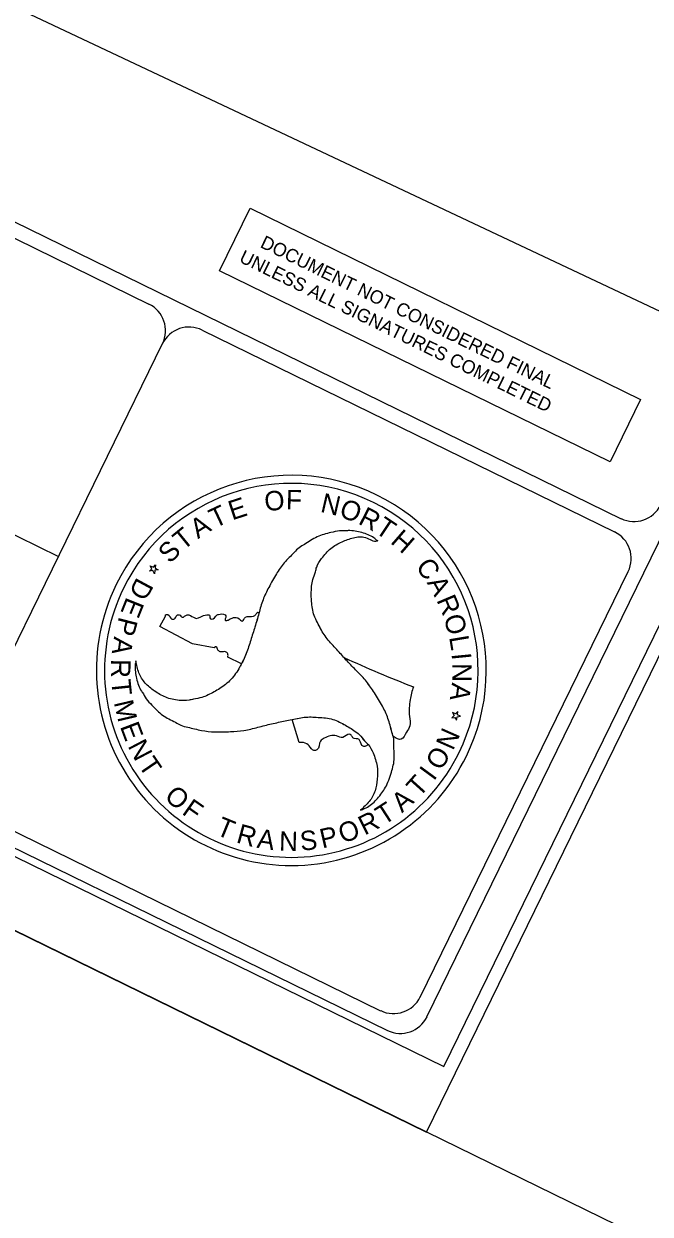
# Model space of a CAD drawing. Extents: x 1517888 to 1526099, y 633375 to 640181.
# Drawn here: x 1520641 to 1521065, y 636669 to 637474 of the extents above; entities that cross this region are included whole.
import ezdxf

# ---------------------------------------------------------------- set-up
doc = ezdxf.new("R2010")
doc.units = 0
for name, color, linetype in [('Sheet Clip Boundary CELL', 7, 'Continuous'), ('Sheet Cutting Line CELL', 7, 'Continuous'), ('Sheet Plot Border Inside CELL', 7, 'Continuous'), ('Sheet Plot Border Outside CELL', 7, 'Continuous'), ('Sheet Sticker Exception Certification CELL', 7, 'Continuous'), ('Sheet Title CELL', 7, 'Continuous')]:
    doc.layers.add(name, color=color, linetype=linetype)

msp = doc.modelspace()

# ---------------------------------------------------------------- linework, layer by layer
at = {"layer": 'Sheet Clip Boundary CELL'}
msp.add_lwpolyline([(1519997.22, 638878.25), (1520677.94, 638519.75), (1521000.39, 638385.3), (1521102.69, 638308.65), (1521171.04, 638278.93), (1521395.99, 638165.98), (1521492.2, 638121.51), (1521760.41, 637993.13), (1521455.66, 637316.28), (1521359.72, 637143.34), (1520289.98, 637647.3), (1519534.36, 638030.12)], close=True, dxfattribs=at)
at = {"layer": 'Sheet Cutting Line CELL'}
msp.add_line((1518399.92, 637954.19), (1521425.45, 636474.47), dxfattribs=at)
at = {"layer": 'Sheet Plot Border Inside CELL'}
msp.add_lwpolyline([(1517931.1, 638233.43), (1520925.19, 636769.09), (1521852.3, 638664.72), (1518858.21, 640129.06)], close=True, dxfattribs=at)
at = {"layer": 'Sheet Plot Border Outside CELL'}
msp.add_lwpolyline([(1521880.11, 638701.1), (1518854.58, 640180.82), (1517888.03, 638204.54), (1520913.56, 636724.82)], close=True, dxfattribs=at)
at = {"layer": 'Sheet Sticker Exception Certification CELL'}
for p, q in [((1520773.47, 637306.71), (1520794.12, 637348.93)), ((1520794.12, 637348.93), (1521058.22, 637219.77)), ((1521037.57, 637177.55), (1520773.47, 637306.71)), ((1521058.21, 637219.74), (1521037.56, 637177.52))]:
    msp.add_line(p, q, dxfattribs=at)
at = {"layer": 'Sheet Title CELL'}
for p, q in [((1518493.77, 638386.96), (1521044.99, 637139.22)), ((1520366.85, 637459.74), (1520725.77, 637284.21)), ((1520268.21, 637307.67), (1520664.67, 637113.77)), ((1520761.7, 637266.63), (1521040.59, 637130.23)), ((1520594.36, 636969.99), (1520734.95, 637257.45)), ((1520880.48, 637124.39), (1520880.15, 637124.24)), ((1520880.48, 637124.39), (1520880.15, 637124.24)), ((1520726.19, 637103.66), (1520727.75, 637105.33)), ((1520727.75, 637105.33), (1520726.7, 637107.37)), ((1520726.7, 637107.37), (1520728.77, 637106.35)), ((1520728.77, 637106.35), (1520730.26, 637107.97)), ((1520730.26, 637107.97), (1520730.03, 637105.74)), ((1520730.03, 637105.74), (1520732.07, 637104.74)), ((1520728.37, 637104.11), (1520726.19, 637103.66)), ((1520729.46, 637102.06), (1520728.37, 637104.11)), ((1520729.78, 637104.34), (1520729.46, 637102.06)), ((1520732.07, 637104.74), (1520729.78, 637104.34)), ((1520733.19, 637066.4), (1520736.92, 637073.41)), ((1520755.24, 637054.58), (1520733.19, 637066.4)), ((1520769.97, 637052.07), (1520755.24, 637054.58)), ((1520788.46, 637041.07), (1520779.14, 637045.76)), ((1520857.59, 637045.48), (1520857.59, 637045.48)), ((1520934.6, 637008.86), (1520933.04, 637007.28)), ((1520934.38, 637006.62), (1520934.6, 637008.86)), ((1520827.38, 636987.99), (1520822.72, 637003.62)), ((1520822.72, 637003.62), (1520822.72, 637003.62)), ((1520932.11, 637006.25), (1520930.55, 637004.58)), ((1520930.55, 637004.58), (1520932.71, 637005)), ((1520933.04, 637007.28), (1520931.01, 637008.27)), ((1520931.01, 637008.27), (1520932.11, 637006.25)), ((1520932.71, 637005), (1520933.78, 637003)), ((1520933.78, 637003), (1520934.14, 637005.26)), ((1520934.14, 637005.26), (1520936.41, 637005.72)), ((1520936.41, 637005.72), (1520934.38, 637006.62)), ((1520940.46, 636978.86), (1520940.46, 636978.86))]:
    msp.add_line(p, q, dxfattribs=at)
for points in [[(1520913.77, 636802.64), (1521818.82, 638653.15)], [(1518227.99, 638093.91), (1520887.01, 636793.44)], [(1520909.18, 636816.02), (1521049.77, 637103.48)], [(1520603.54, 636943.23), (1520882.43, 636806.84)]]:
    msp.add_lwpolyline(points, dxfattribs=at)
for centre, radius, start, end in [((1520716.98, 637266.24), 20, 333.93772, 63.93772), ((1520752.92, 637248.67), 20, 63.93772, 153.93772), ((1520822.06, 637036.74), 131.79, 333.93772, 153.93772), ((1520822.06, 637036.74), 126.3, 333.93772, 153.93772), ((1521053.82, 637157.26), 20, 243.93772, 333.93772), ((1521031.85, 637112.34), 20, 333.93772, 63.93772), ((1520822.06, 637036.74), 131.79, 153.93772, 333.93772), ((1520822.06, 637036.74), 126.3, 153.93772, 333.93772), ((1521150.64, 637675.53), 694.86, 239.61622, 239.71581), ((1521150.64, 637675.53), 694.86, 245.05527, 249.26128), ((1520891.26, 636824.88), 20, 243.93772, 333.93772), ((1520895.85, 636811.51), 20, 243.93772, 333.93772)]:
    msp.add_arc(centre, radius, start, end, dxfattribs=at)
for points in [[(1520880.15, 637124.24), (1520877.83, 637126.25), (1520869.81, 637129.78), (1520860.56, 637131.13), (1520859.67, 637131.09), (1520854.64, 637130.94), (1520848.85, 637129.86), (1520839.46, 637126.93), (1520830.89, 637121.86), (1520827.36, 637119.62), (1520824, 637116.4), (1520817.28, 637109.33), (1520811.97, 637101.93), (1520806.82, 637092.75), (1520802.91, 637084.4), (1520800.15, 637075.27), (1520797.45, 637066.03), (1520794.63, 637057.14), (1520791.62, 637048.05), (1520787.51, 637039.58), (1520787.12, 637038.86), (1520781.2, 637030.58), (1520773.69, 637024.47), (1520765.74, 637020.13), (1520761.48, 637018.44), (1520756, 637017.29), (1520752.88, 637016.6), (1520746.17, 637016.48), (1520737.14, 637018.55), (1520729.43, 637022.89), (1520723.29, 637028.11), (1520719.05, 637035.1), (1520716.96, 637043.17)], [(1520868.87, 636942.39), (1520871.62, 636943.39), (1520878.76, 636948.55), (1520884.56, 636955.89), (1520885.06, 636956.65), (1520887.35, 636961.14), (1520889.34, 636966.73), (1520891.58, 636976.29), (1520891.35, 636986.23), (1520891.26, 636990.4), (1520890.12, 636995), (1520887.37, 637004.31), (1520883.64, 637012.61), (1520878.22, 637021.61), (1520872.89, 637029.13), (1520866.4, 637036.22), (1520859.77, 637043.11), (1520853.55, 637049.94), (1520847.05, 637057.2), (1520841.83, 637064.93), (1520841.46, 637065.68), (1520837.15, 637075), (1520835.65, 637084.56), (1520835.8, 637093.58), (1520836.58, 637098.02), (1520838.33, 637103.39), (1520839.21, 637106.52), (1520842.55, 637112.28), (1520848.87, 637119.15), (1520856.4, 637123.6), (1520864.01, 637126.27), (1520872.22, 637126.43), (1520880.15, 637124.24), (1520880.48, 637124.39)], [(1520736.92, 637073.41), (1520737, 637074.19), (1520738.57, 637074.38), (1520741.24, 637071.38), (1520743.63, 637072), (1520744.26, 637073.47), (1520746.3, 637074.26), (1520748.35, 637072.69), (1520751.71, 637074.31), (1520753.83, 637073.84), (1520757.83, 637071.88), (1520764.9, 637074.33), (1520767.04, 637073.64), (1520766.91, 637072.13), (1520768.02, 637071.29), (1520771.98, 637074.22), (1520772.78, 637074.53), (1520777.22, 637074.18), (1520777.86, 637073), (1520777.28, 637071.11), (1520777.63, 637070.5), (1520779.29, 637070.77), (1520781.97, 637072.07), (1520785.8, 637072.16), (1520789.06, 637070.04), (1520791.05, 637072.59), (1520796.46, 637073.34), (1520798.11, 637074.57), (1520799.14, 637076.16)], [(1520800.21, 637075.5), (1520800.15, 637075.27), (1520797.45, 637066.03), (1520794.63, 637057.14), (1520791.62, 637048.05), (1520788.43, 637041.09)], [(1520779.14, 637045.76), (1520779.07, 637047.92), (1520777.51, 637049.34), (1520774.41, 637049.24), (1520772.61, 637050.26), (1520771.29, 637052.73), (1520769.97, 637052.07)], [(1520716.96, 637043.17), (1520716.49, 637040.09), (1520717.41, 637031.38), (1520720.81, 637022.67), (1520721.3, 637022), (1520723.98, 637017.6), (1520727.82, 637013.2), (1520735.05, 637006.45), (1520743.68, 637001.7), (1520747.35, 636999.69), (1520752.05, 636998.35), (1520761.32, 636996.16), (1520770.33, 636995.19), (1520780.93, 636995.35), (1520790.03, 636996.17), (1520799.42, 636998.31), (1520808.75, 637000.66), (1520817.87, 637002.6), (1520827.27, 637004.48), (1520836.64, 637005.24), (1520837.61, 637005.16), (1520847.75, 637004.2), (1520856.69, 637000.79), (1520864.34, 636996.17), (1520868.09, 636993.25), (1520871.64, 636989.04), (1520874.02, 636986.7), (1520877.34, 636980.95), (1520880.02, 636972.11), (1520880.16, 636963.35), (1520878.68, 636955.33), (1520874.74, 636948.17), (1520868.87, 636942.39)], [(1520891, 636992.09), (1520890.12, 636995), (1520887.37, 637004.31), (1520883.64, 637012.61), (1520878.22, 637021.61), (1520872.89, 637029.13), (1520866.4, 637036.22), (1520859.77, 637043.11), (1520857.59, 637045.48)], [(1520904.56, 637025.68), (1520902.39, 637016.96), (1520901.98, 637005.64), (1520902.16, 636999.25), (1520899.94, 636994.9), (1520896.37, 636990.17), (1520891.06, 636992.11)], [(1520822.72, 637003.62), (1520827.27, 637004.48), (1520836.64, 637005.24), (1520837.61, 637005.16), (1520847.75, 637004.2), (1520856.69, 637000.79), (1520864.34, 636996.17), (1520868.09, 636993.25), (1520871.64, 636989.04), (1520873.82, 636986.84)], [(1520873.77, 636986.82), (1520871.67, 636985.28), (1520869.81, 636986.02), (1520867.91, 636990.04), (1520863.71, 636991.14), (1520862.45, 636993.01), (1520861.31, 636993.61), (1520856.84, 636991.5), (1520852.64, 636992.51), (1520844.28, 636990.98), (1520841.73, 636988.97), (1520839.41, 636983.06), (1520837.35, 636982.68), (1520835.66, 636983.85), (1520832.59, 636987.18), (1520827.38, 636987.99)]]:
    msp.add_spline(points, degree=3, dxfattribs=at)

# ---------------------------------------------------------------- texts
at = {"layer": 'Sheet Sticker Exception Certification CELL'}
for s, p in [('DOCUMENT NOT CONSIDERED FINAL', (1520800.37, 637322.84)), ('UNLESS ALL SIGNATURES COMPLETED', (1520786.18, 637312.99))]:
    msp.add_text(s, height=9, rotation=333.93772, dxfattribs=at).set_placement(p)
at = {"layer": 'Sheet Title CELL'}
for s, height, rotation, p in [('E', 13.1, 18.09466, (1520782.04, 637138.01)), ('O', 13.16, 6.15528, (1520804.52, 637144.14)), ('F', 13.17, 359.00844, (1520818.35, 637145.56)), ('N', 13.14, 346.9215, (1520841.16, 637143.92)), ('T', 13.11, 25.21029, (1520770.38, 637132.58)), ('O', 13.17, 339.42339, (1520853.66, 637140.94)), ('R', 13.14, 332.81346, (1520866.66, 637136.06)), ('A', 13.18, 32.26551, (1520758.88, 637125.33)), ('T', 13.17, 326.16383, (1520877.86, 637130.32)), ('T', 13.17, 39.31782, (1520748.84, 637117.33)), ('H', 13.12, 319.07911, (1520888.49, 637123.08)), ('S', 13.13, 45.69397, (1520740.07, 637108.39)), ('C', 13.1, 306.73676, (1520905.65, 637106.6)), ('D', 13.14, 241.79072, (1520717.78, 637100.16)), ('A', 13.13, 299.23973, (1520913.45, 637096.04)), ('E', 13.08, 248.07861, (1520710.77, 637086.81)), ('R', 13.13, 292.87579, (1520920.05, 637084.29)), ('O', 13.16, 285.75618, (1520924.9, 637072.7)), ('P', 13.14, 255.61101, (1520705.69, 637073.47)), ('A', 13.12, 262.20358, (1520702.21, 637059.86)), ('L', 13.11, 279.52251, (1520928.71, 637059.23)), ('R', 13.14, 269.27222, (1520700.26, 637044.42)), ('I', 13.16, 275.53316, (1520930.35, 637047.99)), ('N', 13.14, 269.83306, (1520930.87, 637041.6)), ('T', 13.13, 275.92275, (1520700.21, 637029.92)), ('A', 13.14, 262.40108, (1520930.74, 637028.71)), ('M', 13.1, 283.15779, (1520701.97, 637015.1)), ('E', 13.11, 290.62456, (1520706.04, 636998.89)), ('N', 13.14, 66.14586, (1520931.38, 636982.09)), ('N', 13.17, 297.59611, (1520711.19, 636985.68)), ('T', 13.12, 304.43811, (1520718.19, 636972.6)), ('O', 13.09, 58.89784, (1520923.3, 636968.42)), ('I', 13.17, 53.76221, (1520918.39, 636961.57)), ('T', 13.12, 48.11231, (1520908.52, 636950.48)), ('O', 13.13, 317.74179, (1520735.55, 636950.58)), ('A', 13.17, 41.02788, (1520896.89, 636940.12)), ('F', 13.13, 324.90702, (1520747.46, 636940.06)), ('T', 13.1, 32.94084, (1520884.53, 636931.82)), ('T', 13.1, 337.81625, (1520770.39, 636926.06)), ('R', 13.16, 26.84105, (1520871.62, 636925.08)), ('R', 13.15, 344.77287, (1520784.24, 636920.59)), ('A', 13.1, 351.526, (1520798.3, 636916.98)), ('S', 13.09, 5.7681, (1520828.56, 636914.83)), ('P', 13.13, 12.95995, (1520843.01, 636916.38)), ('O', 13.17, 19.65194, (1520856.7, 636919.64)), ('N', 13.1, 358.55763, (1520813.7, 636914.93))]:
    msp.add_text(s, height=height, rotation=rotation, dxfattribs=at).set_placement(p)

doc.saveas('drawing.dxf')
